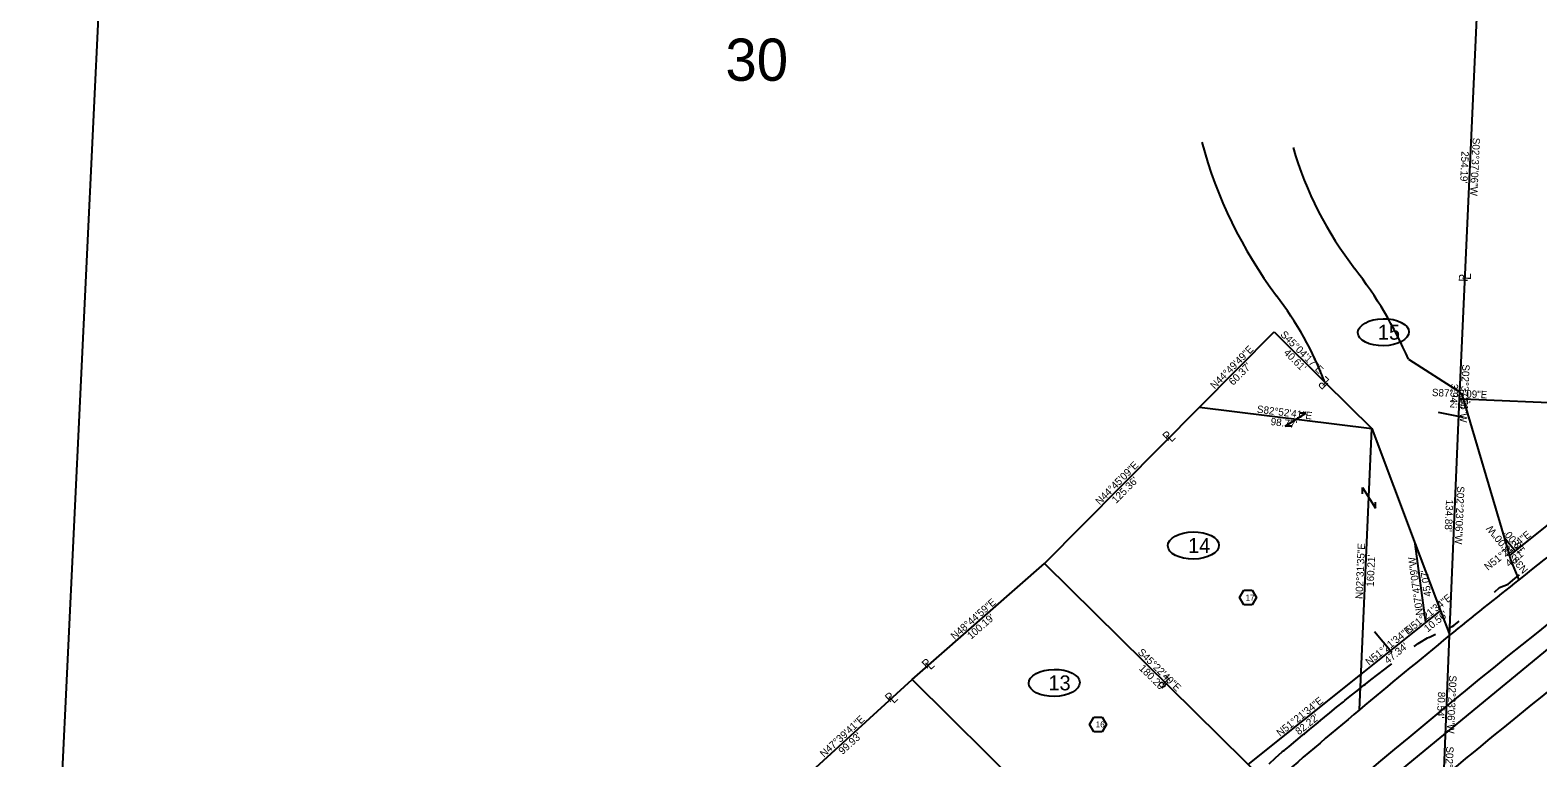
# Model space of a CAD drawing. Extents: x 1145508 to 2262867, y -3126236 to 2021677.
# Drawn here: x 1146803 to 1147661, y 2017486 to 2017900 of the extents above; entities that cross this region are included whole.
import ezdxf

# ---------------------------------------------------------------- set-up
doc = ezdxf.new("R2010")
doc.units = 0
for name, color, linetype in [('Default', 7, 'Continuous'), ('DSN_RDWY_Const Limits', 7, 'Continuous'), ('DSN_ROW_Annotation', 7, 'Continuous'), ('DSN_ROW_Line', 7, 'Continuous'), ('DSN_ROW_Line-Annotation', 7, 'Continuous'), ('DSN_ROW_Prop-Line', 7, 'Continuous'), ('DSN_ROW_Prop-Line-Annotation', 7, 'Continuous'), ('E_Const Align', 7, 'Continuous'), ('EX_QSECTION', 7, 'Continuous'), ('EX_ROW', 7, 'Continuous'), ('EX_ROW_ANNOT', 7, 'Continuous'), ('EX_SECTION', 7, 'Continuous'), ('EX_SIGN', 7, 'Continuous'), ('EX_SUBDIV_ANNOT', 7, 'Continuous'), ('SHET_Annotations', 7, 'Continuous')]:
    doc.layers.add(name, color=color, linetype=linetype)

msp = doc.modelspace()

# ---------------------------------------------------------------- linework, layer by layer
at = {"layer": 'Default'}
msp.add_arc((1150521.47, 2013976.61), 4583.66, 127.59365, 131.75523, dxfattribs=at)
at = {"layer": 'DSN_RDWY_Const Limits'}
for points in [[(1147636.06, 2017580.62), (1147638.9, 2017583.22), (1147643.75, 2017585.19), (1147647.61, 2017588.37), (1147648.42, 2017589.03), (1147648.51, 2017589.1), (1147649.17, 2017589.63), (1147650.2, 2017590.46)], [(1147610.03, 2017560.19), (1147611.81, 2017561.06), (1147612.75, 2017561.52), (1147612.9, 2017561.59), (1147615.85, 2017564.01)], [(1147590.34, 2017549.7), (1147592.6, 2017551.36), (1147593.41, 2017551.95), (1147597.76, 2017554.52), (1147598.71, 2017554.95), (1147598.9, 2017555.03), (1147602.49, 2017556.65)], [(1147507.73, 2017482.95), (1147511.41, 2017486.35), (1147515.19, 2017489.63), (1147515.88, 2017490.2), (1147516.21, 2017490.47), (1147519.04, 2017492.81), (1147522.9, 2017495.99), (1147526.76, 2017499.17), (1147527.45, 2017499.75), (1147527.77, 2017500.02), (1147530.61, 2017502.36), (1147534.47, 2017505.54), (1147538.33, 2017508.71), (1147539.08, 2017509.32), (1147539.31, 2017509.51), (1147542.21, 2017511.88), (1147546.09, 2017515.03), (1147549.98, 2017518.17), (1147550.8, 2017518.83), (1147550.87, 2017518.89), (1147553.88, 2017521.3), (1147557.78, 2017524.42), (1147561.69, 2017527.55), (1147562.51, 2017528.21), (1147562.59, 2017528.27), (1147565.62, 2017530.64), (1147569.58, 2017533.69), (1147573.54, 2017536.75), (1147574.38, 2017537.39), (1147574.45, 2017537.45), (1147577.5, 2017539.8)]]:
    msp.add_lwpolyline(points, dxfattribs=at)
at = {"layer": 'DSN_ROW_Line'}
for p, q in [((1147647.75, 2017603.95), (1147749, 2017684.9)), ((1147596.97, 2017563.36), (1147590.87, 2017608.02)), ((1147647.75, 2017603.95), (1147641.4, 2017611.67)), ((1147644.46, 2017601.32), (1147647.75, 2017603.95)), ((1147559.99, 2017533.8), (1147596.97, 2017563.36)), ((1147596.97, 2017563.36), (1147605.22, 2017569.95)), ((1147495.77, 2017482.46), (1147559.99, 2017533.8))]:
    msp.add_line(p, q, dxfattribs=at)
at = {"layer": 'DSN_ROW_Line-Annotation'}
for centre in [(1147572.73, 2017728.44), (1147464.62, 2017607.11), (1147385.45, 2017528.91)]:
    msp.add_ellipse(centre, major_axis=(14.54, 0.23), ratio=0.529773, dxfattribs=at)
at = {"layer": 'DSN_ROW_Prop-Line'}
for p, q in [((1147468.12, 2017685.87), (1147510.68, 2017728.68)), ((1147510.68, 2017728.68), (1147539.43, 2017700.01)), ((1147379.86, 2017596.84), (1147468.12, 2017685.87)), ((1147468.12, 2017685.87), (1147566.13, 2017673.62)), ((1147559.07, 2017513.57), (1147566.13, 2017673.62)), ((1147304.54, 2017530.78), (1147379.86, 2017596.84)), ((1147379.86, 2017596.84), (1147508.13, 2017470.27)), ((1147230.67, 2017463.48), (1147304.54, 2017530.78)), ((1147304.54, 2017530.78), (1147432.84, 2017403.92))]:
    msp.add_line(p, q, dxfattribs=at)
at = {"layer": 'DSN_ROW_Prop-Line-Annotation'}
for p, q in [((1147516.83, 2017675), (1147528.69, 2017682.39)), ((1147520.38, 2017675), (1147516.83, 2017675)), ((1147528.69, 2017682.39), (1147525.14, 2017682.39)), ((1147560.93, 2017636.59), (1147560.93, 2017640.14)), ((1147560.93, 2017640.14), (1147568.31, 2017628.28)), ((1147568.31, 2017628.28), (1147568.31, 2017631.83))]:
    msp.add_line(p, q, dxfattribs=at)
at = {"layer": 'E_Const Align'}
msp.add_line((1146840, 2016868.61), (1147825.51, 2017679.08), dxfattribs=at)
at = {"layer": 'EX_QSECTION'}
for p, q in [((1147627.67, 2017948.45), (1147616.06, 2017694.52)), ((1147616.06, 2017694.52), (1147615.88, 2017690.59)), ((1147615.88, 2017690.59), (1147610.26, 2017555.82)), ((1147615.88, 2017690.59), (1147618.09, 2017690.49)), ((1147618.09, 2017690.49), (1147749, 2017684.9)), ((1147610.26, 2017555.82), (1147606.91, 2017475.35))]:
    msp.add_line(p, q, dxfattribs=at)
at = {"layer": 'EX_ROW'}
for p, q in [((1147586.97, 2017713.15), (1147616.06, 2017694.52)), ((1147539.43, 2017700.01), (1147566.13, 2017673.62)), ((1147616.06, 2017694.52), (1147616.25, 2017694.39)), ((1147616.25, 2017694.39), (1147617.22, 2017693.44)), ((1147617.22, 2017693.44), (1147618.09, 2017690.49)), ((1147618.09, 2017690.49), (1147641.4, 2017611.67)), ((1147566.13, 2017673.62), (1147590.87, 2017608.02)), ((1147590.87, 2017608.02), (1147605.22, 2017569.95)), ((1147641.4, 2017611.67), (1147644.46, 2017601.32)), ((1147644.46, 2017601.32), (1147645.13, 2017599.05)), ((1147645.13, 2017599.05), (1147649.81, 2017587.63)), ((1147605.22, 2017569.95), (1147610.11, 2017556.96)), ((1147610.11, 2017556.96), (1147610.26, 2017555.82))]:
    msp.add_line(p, q, dxfattribs=at)
for centre, radius, start, end in [((1147719.44, 2017904.11), 258.99, 195.11642, 216.7359), ((1147721.81, 2017892.49), 208.99, 196.39693, 217.73594), ((1147365.95, 2017617.09), 240.99, 23.49161, 37.73571), ((1147360.84, 2017632.31), 190.99, 20.75781, 37.73561), ((1150521.47, 2013976.61), 4613.66, 127.59365, 128.49351), ((1150521.47, 2013976.61), 4553.66, 127.59365, 129.79541), ((1150521.47, 2013976.61), 4613.66, 128.49351, 129.12379), ((1150521.47, 2013976.61), 4613.66, 129.12379, 129.9481), ((1150521.47, 2013976.61), 4613.66, 129.9481, 130.77845)]:
    msp.add_arc(centre, radius, start, end, dxfattribs=at)
at = {"layer": 'EX_SECTION'}
msp.add_line((1146895.16, 2019036.08), (1146802.69, 2017096.93), dxfattribs=at)
at = {"layer": 'EX_SIGN'}
for p, q in [((1147603.95, 2017682.95), (1147618.14, 2017680.14)), ((1147567.6, 2017558.11), (1147577.64, 2017546.4))]:
    msp.add_line(p, q, dxfattribs=at)
at = {"layer": 'EX_SUBDIV_ANNOT'}
for p, q in [((1147490.85, 2017577.46), (1147493.25, 2017581.62)), ((1147493.25, 2017581.62), (1147498.05, 2017581.62)), ((1147498.05, 2017581.62), (1147500.45, 2017577.46)), ((1147493.25, 2017573.31), (1147490.85, 2017577.46)), ((1147498.05, 2017573.31), (1147493.25, 2017573.31)), ((1147500.45, 2017577.46), (1147498.05, 2017573.31)), ((1147405.57, 2017505.29), (1147407.97, 2017509.45)), ((1147407.97, 2017501.13), (1147405.57, 2017505.29)), ((1147407.97, 2017509.45), (1147412.77, 2017509.45)), ((1147412.77, 2017509.45), (1147415.17, 2017505.29)), ((1147415.17, 2017505.29), (1147412.77, 2017501.13)), ((1147412.77, 2017501.13), (1147407.97, 2017501.13))]:
    msp.add_line(p, q, dxfattribs=at)

# ---------------------------------------------------------------- texts
at = {"layer": 'DSN_ROW_Annotation'}
for s, rotation, p in [('S45°04\'17"E', 315.07127, (1147513.82, 2017726.82)), ('N44°49\'49"E', 45.16972, (1147476.74, 2017695.81)), ("40.61'", 315.07127, (1147515.68, 2017716.49)), ("60.37'", 45.16972, (1147487.27, 2017697.9)), ('S82°52\'41"E', 352.87811, (1147500.61, 2017682.72)), ("98.77'", 352.87811, (1147508.41, 2017675.7)), ('N44°45\'09"E', 45.24755, (1147411.34, 2017629.88)), ("125.36'", 45.24755, (1147420.67, 2017630.76)), ('N51°21\'34"E', 38.64061, (1147632.22, 2017592.69)), ('N39°26\'00"W', 129.43332, (1147655.35, 2017593.29)), ("10.00'", 129.43332, (1147653.69, 2017604.76)), ('N02°31\'35"E', 87.47348, (1147560.95, 2017576.59)), ("160.21'", 87.47348, (1147567.26, 2017583.52)), ('N07°47\'09"W', 97.78573, (1147595.47, 2017567.67)), ("4.21'", 38.64061, (1147644.25, 2017594.63)), ("45.07'", 97.78573, (1147600.08, 2017578.3)), ('N48°44\'59"E', 41.25015, (1147328.78, 2017553.24)), ('N51°21\'34"E', 38.64061, (1147587.21, 2017556.71)), ("100.19'", 41.25015, (1147338.15, 2017553.48)), ("10.56'", 38.64061, (1147597.91, 2017557.58)), ('N51°21\'34"E', 38.64061, (1147564.6, 2017538.63)), ('S45°22\'49"E', 315.38025, (1147432.69, 2017545.97)), ("47.34'", 38.64061, (1147575.3, 2017539.5)), ("180.20'", 315.38025, (1147433.39, 2017536.85)), ('N51°21\'34"E', 38.64061, (1147514, 2017498.18)), ('N47°39\'41"E', 42.33869, (1147254.39, 2017486.31)), ("82.22'", 38.64061, (1147524.7, 2017499.05)), ("99.93'", 42.33869, (1147265.01, 2017487.87))]:
    msp.add_text(s, height=4.2, rotation=rotation, dxfattribs=at).set_placement(p)
at = {"layer": 'DSN_ROW_Line-Annotation'}
for s, p in [('15', (1147569.57, 2017724.23)), ('14', (1147461.62, 2017602.9)), ('13', (1147382.13, 2017524.7))]:
    msp.add_text(s, height=8.5, dxfattribs=at).set_placement(p)
at = {"layer": 'DSN_ROW_Prop-Line-Annotation'}
for s, rotation, p in [('P', 88.86651, (1147620.65, 2017757.15)), ('L', 88.86651, (1147622.59, 2017758.27)), ('L', 135.16895, (1147542.38, 2017701.12)), ('P', 135.16895, (1147541.85, 2017698.94)), ('P', 43.74001, (1147449.94, 2017666.19)), ('L', 43.74001, (1147452.11, 2017665.61)), ('P', 42.70474, (1147312.87, 2017536.69)), ('L', 42.70474, (1147315.03, 2017536.07)), ('P', 135.16895, (1147450.83, 2017528.75)), ('L', 135.16895, (1147451.36, 2017530.93)), ('P', 42.96201, (1147291.93, 2017517.52)), ('L', 42.96201, (1147294.09, 2017516.91))]:
    msp.add_text(s, height=5, rotation=rotation, dxfattribs=at).set_placement(p)
at = {"layer": 'EX_ROW_ANNOT'}
for s, rotation, p in [('S02°37\'06"W', 267.38153, (1147623.57, 2017839.2)), ('S02°37\'06"W', 267.38153, (1147623.57, 2017839.2)), ("254.19'", 267.38153, (1147617.22, 2017831.57)), ("254.19'", 267.38153, (1147617.22, 2017831.57)), ('S02°37\'06"W', 267.38153, (1147617.68, 2017710.26)), ('S02°37\'06"W', 267.38153, (1147617.68, 2017710.26)), ('S87°33\'09"E', 357.55261, (1147600.28, 2017692.16)), ('S87°33\'09"E', 357.55261, (1147600.28, 2017692.16)), ("3.94'", 267.38153, (1147611.17, 2017699.23)), ("3.94'", 267.38153, (1147611.17, 2017699.23)), ("2.22'", 357.55261, (1147610.33, 2017685.72)), ("2.22'", 357.55261, (1147610.33, 2017685.72)), ('S02°23\'06"W', 267.61494, (1147614.71, 2017640.92)), ('S02°23\'06"W', 267.61494, (1147614.71, 2017640.92)), ("134.88'", 267.61494, (1147608.38, 2017633.27)), ("134.88'", 267.61494, (1147608.38, 2017633.27)), ('S02°23\'06"W', 267.61494, (1147610.23, 2017533.3)), ('S02°23\'06"W', 267.61494, (1147610.23, 2017533.3)), ("80.54'", 267.61494, (1147603.83, 2017523.94)), ("80.54'", 267.61494, (1147603.83, 2017523.94)), ('S02°23\'06"W', 267.61494, (1147608.54, 2017492.88)), ('S02°23\'06"W', 267.61494, (1147608.54, 2017492.88))]:
    msp.add_text(s, height=4.2, rotation=rotation, dxfattribs=at).set_placement(p)
at = {"layer": 'EX_SUBDIV_ANNOT'}
for s, p in [('17', (1147494.34, 2017575.75)), ('16', (1147409.06, 2017503.58))]:
    msp.add_text(s, height=3.418, dxfattribs=at).set_placement(p)
at = {"layer": 'SHET_Annotations'}
msp.add_text('30', height=24, dxfattribs=at).set_placement((1147198.32, 2017871.56))

doc.saveas('drawing.dxf')
